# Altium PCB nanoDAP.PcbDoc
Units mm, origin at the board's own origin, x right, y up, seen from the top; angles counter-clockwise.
Board outline 76.68 x 40 mm, 2 copper layers (Top Layer, Bottom Layer); 20 components, 42 nets, 124 pads, 17 vias.
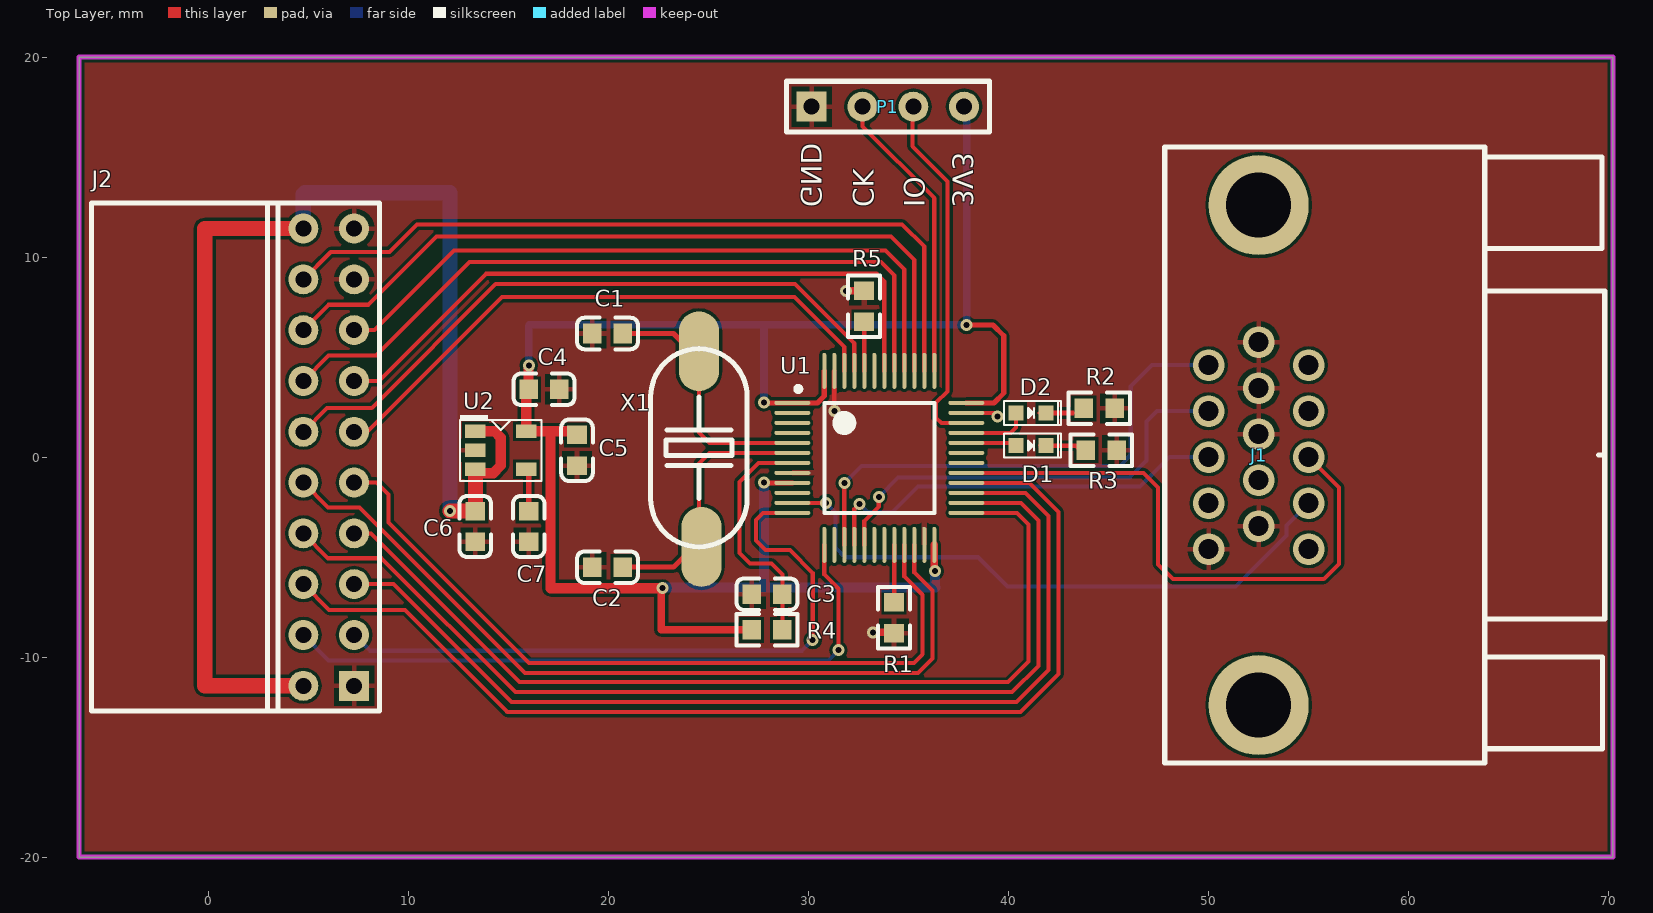
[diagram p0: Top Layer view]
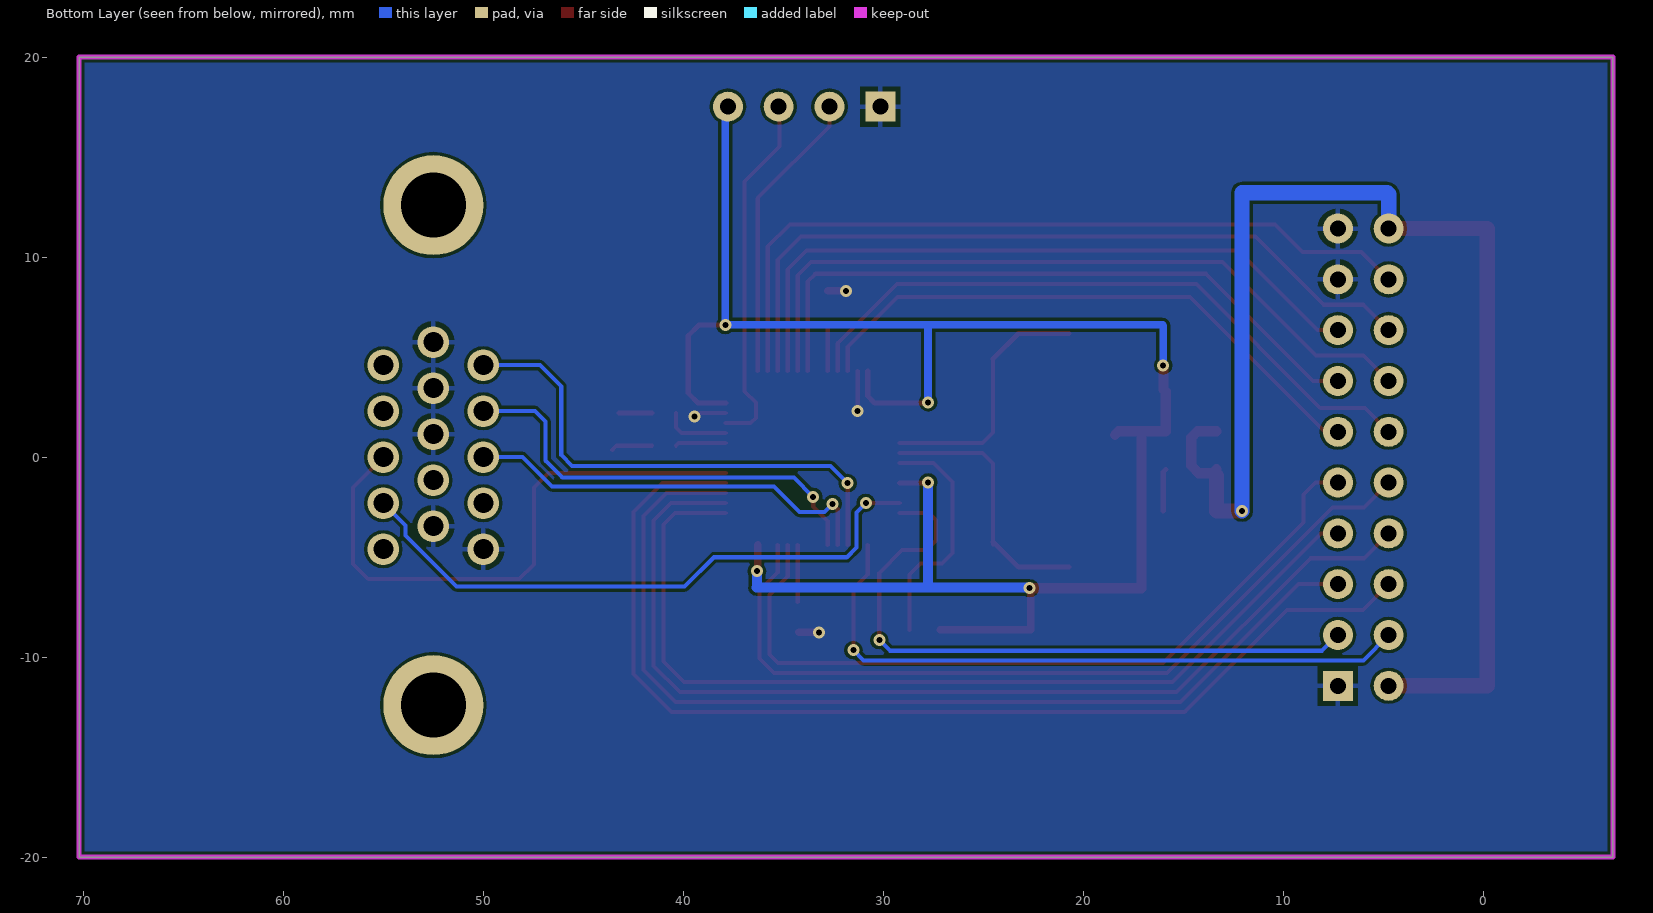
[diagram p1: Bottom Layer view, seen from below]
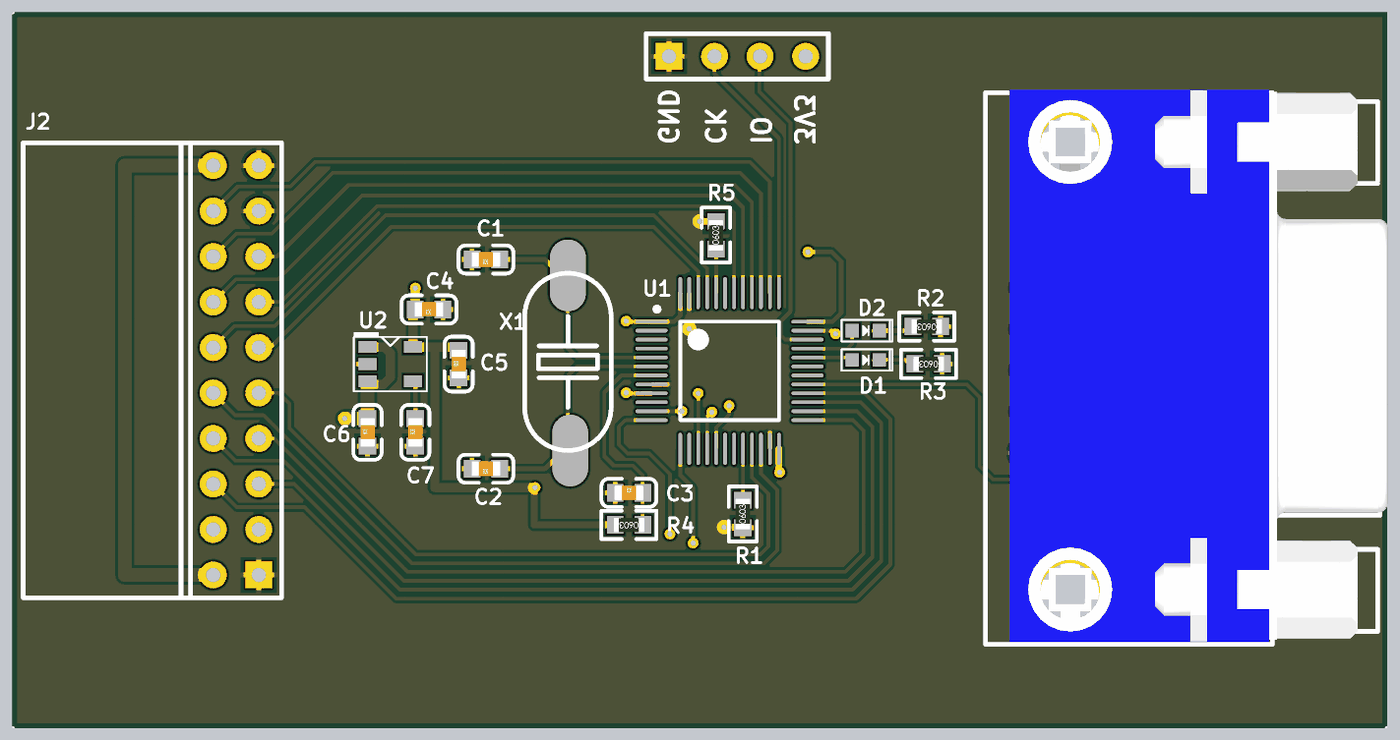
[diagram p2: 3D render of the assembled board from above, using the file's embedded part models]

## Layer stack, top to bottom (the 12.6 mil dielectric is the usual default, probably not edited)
Top Solder: solder mask 0.0102, Solder Resist, Dk 3.5
Top Layer: signal copper 0.0356
Dielectric 1: dielectric 0.32, FR-4, Dk 4.8
Bottom Layer: signal copper 0.0356
Bottom Solder: solder mask 0.0102, Solder Resist, Dk 3.5

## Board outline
-6.477,-20 -6.477,20 70.206,20 70.206,-20

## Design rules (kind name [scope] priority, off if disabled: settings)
Clearance [All] p1: gap=0.152 ignorepadtopadclearanceinfootprint=FALSE
DiffPairsRouting [All] p1: maxlimit=0.254 minlimit=0.254 mostfreqgap=0.254 toplayer_minwidth=0.203 toplayer_maxwidth=0.381 toplayer_prefwidth=0.381 bottomlayer_minwidth=0.203 bottomlayer_maxwidth=0.381 bottomlayer_prefwidth=0.381 maxuncoupledlength=12.7
HoleSize [All] p1 off: absolutevalues=TRUE maxlimit=2.54 minlimit=0.025 maxpercent=80.000 minpercent=20.000
PolygonConnect [All] p1: thpad.connectstyle=Relief thpad.reliefconductorwidth=0.254 thpad.reliefentries=4 thpad.polygonreliefangle="90 Angle" thpad.airgapwidth=0.254 smdpad.connectstyle=Relief smdpad.reliefconductorwidth=0.254 smdpad.reliefentries=4 smdpad.polygonreliefangle="90 Angle" smdpad.airgapwidth=0.254 via.connectstyle=Direct via.reliefconductorwidth=0.254 via.reliefentries=4 via.polygonreliefangle="90 Angle" via.airgapwidth=0.254
RoutingVias [All] p1: holewidth=0.3 width=0.6 viastyle="Through Hole" minholewidth=0.3 minwidth=0.6 maxholewidth=0.3 maxwidth=0.6
SolderMaskExpansion [All] p1: expansion=0.102
Width [All] p1: maxlimit=2.54 minlimit=0.152 preferedwidth=0.254
28 further rules are at their usual default settings.

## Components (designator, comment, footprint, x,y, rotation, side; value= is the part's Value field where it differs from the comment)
C1 "C0603" 0603_C 19.939,6.185 r180 top value=20pF
C2 "C0603" 0603_C 19.939,-5.499 r180 top value=20pF
C3 "C0603" 0603_C 27.915,-6.845 r0 top value=0.1uF
C4 "1uf" 0603_C 16.764,3.391 r180 top value=1uF
C5 "104" 0603_C 18.415,0.343 r90 top value=0.1uF
C6 "1uf" 0603_C 13.335,-3.467 r90 top value=1uF
C7 "223" 0603_C 16.002,-3.467 r90 top
D1 "RED" 0603_LED 41.123,0.572 r0 top
D2 "BLUE" 0603_LED 41.123,2.21 r0 top
J1 "VGA_FEMALE" VGA15B 50,0 r270 top
J2 "IDC20" IDC20 6,0 r90 top
P1 "Header 4" HEADER_4x1 30.15,17.526 r0 top
R1 "R0603" 0603_R 34.265,-8.026 r90 top value=10K
R2 "R0603" 0603_R 44.526,2.438 r180 top value=10K
R3 "R0603" 0603_R 44.628,0.356 r180 top value=10K
R4 "R0603" 0603_R 27.915,-8.636 r180 top value=10K
R5 "R0603" 0603_R 32.766,7.544 r90 top value=10K
U1 "STM32F103C8T6" LQFP48_N 33.528,-0.038 r0 top locked
U2 "RT9193-33" SOT23-5 14.605,0.343 r90 top
X1 "XTAL" 49SMD 24.511,0.47 r270 top value=8MHz

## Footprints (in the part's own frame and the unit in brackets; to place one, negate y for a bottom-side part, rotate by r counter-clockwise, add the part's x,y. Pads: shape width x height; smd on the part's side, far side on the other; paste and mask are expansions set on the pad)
49SMD [mm]
  oval 4x2 smd: 1(-4.826,0) 2(4.953,0.127)
  silkscreen extent -4.95,-2.41 4.95,2.41
0603_C [mm]
  rect 0.93x0.98 smd: 1(-0.77,0) 2(0.77,0)
  silkscreen extent -1.53,-0.79 1.54,0.79, body extent -0.8,-0.4 0.8,0.4, height 0.3
0603_LED [mm]
  rect 0.75x0.75 smd: 1(-0.75,0) 2(0.75,0)
  silkscreen extent -1.35,-0.6 1.5,0.6
0603_R [mm]
  rect 0.93x0.98 smd: 1(-0.77,0) 2(0.77,0)
  silkscreen extent -1.53,-0.79 1.54,0.79, body extent -0.85,-0.4 0.85,0.4, height 0.56
HEADER_4x1 [mm]
  rect 1.5x1.5 hole 0.8: 1(0,0)
  round 1.5 hole 0.8: 2(2.54,0) 3(5.08,0) 4(7.62,0)
  silkscreen extent -1.27,-1.27 8.89,1.27
IDC20 [mm]
  rect 1.5x1.5 hole 0.8: 1(-11.43,-1.27)
  round 1.5 hole 0.8: 2(-11.43,1.27) 3(-8.89,-1.27) 4(-8.89,1.27) 5(-6.35,-1.27) 6(-6.35,1.27) 7(-3.81,-1.27) 8(-3.81,1.27) 9(-1.27,-1.27) 10(-1.27,1.27) 11(1.27,-1.27) 12(1.27,1.27) 13(3.81,-1.27) 14(3.81,1.27) 15(6.35,-1.27) 16(6.35,1.27) 17(8.89,-1.27) 18(8.89,1.27) 19(11.43,-1.27) 20(11.43,1.27)
  silkscreen extent -12.7,-2.54 12.7,11.87
LQFP48_N [mm]
  oval 1.8x0.2 smd: 1(-4.35,2.75) 2(-4.35,2.25) 3(-4.35,1.75) 4(-4.35,1.25) 5(-4.35,0.75) 6(-4.35,0.25) 7(-4.35,-0.25) 8(-4.35,-0.75) 9(-4.35,-1.25) 10(-4.35,-1.75) 11(-4.35,-2.25) 12(-4.35,-2.75) 25(4.35,-2.75) 26(4.35,-2.25) 27(4.35,-1.75) 28(4.35,-1.25) 29(4.35,-0.75) 30(4.35,-0.25) 31(4.35,0.25) 32(4.35,0.75) 33(4.35,1.25) 34(4.35,1.75) 35(4.35,2.25) 36(4.35,2.75)
  oval 0.2x1.8 smd: 13(-2.75,-4.35) 14(-2.25,-4.35) 15(-1.75,-4.35) 16(-1.25,-4.35) 17(-0.75,-4.35) 18(-0.25,-4.35) 19(0.25,-4.35) 20(0.75,-4.35) 21(1.25,-4.35) 22(1.75,-4.35) 23(2.25,-4.35) 24(2.75,-4.35) 37(2.75,4.35) 38(2.25,4.35) 39(1.75,4.35) 40(1.25,4.35) 41(0.75,4.35) 42(0.25,4.35) 43(-0.25,4.35) 44(-0.75,4.35) 45(-1.25,4.35) 46(-1.75,4.35) 47(-2.25,4.35) 48(-2.75,4.35)
  silkscreen extent -4.17,-2.75 2.75,3.57
SOT23-5 [mil]
  rect 26x40 smd: 1(37.4,50) 2(0,50) 3(-37.4,50) 4(-37.4,-50) 5(37.4,-50)
  silkscreen extent -60,-80 70,80
VGA15B [mm] "15针通讯接口"
  round 1.58 hole 1: 1(-4.6,0) 2(-2.3,0) 3(0,0) 4(2.3,0) 5(4.6,0) 6(-5.75,2.5) 7(-3.45,2.5) 8(-1.15,2.5) 9(1.15,2.5) 10(3.45,2.5) 11(-4.6,5) 12(-2.3,5) 13(0,5) 14(2.3,5) 15(4.6,5)
  round 5 hole 3.25: 16(-12.6,2.5) 17(12.4,2.5)
  silkscreen extent -15.5,-2.2 15.3,19.8, body extent -15.66,-0.87 15.15,20.23, height 12.77

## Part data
C1 C2 C3: "Capacitor"
C4 C5 C6 C7: library part CAP, "Capacitor"
D1 D2: library part D0603, "Typical RED, GREEN, YELLOW, AMBER GaAs LED"
P1: "Header, 4-Pin"
R1 R2 R3 R4 R5: "Resistor"
U1: "LowPower MCU"

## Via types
v1: diameter 0.6, hole 0.3, Top Layer to Bottom Layer, 17 vias

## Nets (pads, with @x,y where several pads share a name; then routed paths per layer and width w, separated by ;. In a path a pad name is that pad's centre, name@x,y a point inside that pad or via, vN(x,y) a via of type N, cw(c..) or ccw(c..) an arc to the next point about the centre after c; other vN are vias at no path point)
3V3: C4.2 C5.2 P1.4 R4.2 U1.1 U1.9 U1.24 U1.36 U1.48 U2.5 | length 98.5
  Top Layer w0.254: v1(27.762,-1.257) 27.793,-1.288 U1.9 ; v1@27.793,2.712 U1.1 30.436,2.712 30.778,3.054 U1.48 ; v1@36.278,-5.658 v1(36.322,-5.702) ; U1.36 39.262,2.712 39.751,3.2 39.751,6.071 39.218,6.604 v1(37.897,6.604)
  Top Layer w0.381: v1(22.682,-6.553) 22.631,-6.604 22.631,-8.636 R4.2 ; v1@36.278,-5.658 U1.24
  Top Layer w0.508: v1(16.002,4.585) 15.994,4.577 C4.2 15.875,3.272 U2.5 17.094,1.293 ; C5.2 18.235,1.293 17.094,1.293 ; v1(22.682,-6.553) 17.094,-6.553 17.094,1.293
  Bottom Layer w0.381: v1(16.002,4.585) 16.002,6.579 16.04,6.617 37.884,6.617 v1(37.897,6.604) ; v1(27.762,2.743) 27.762,6.566 ; v1@37.91,6.617 P1.4@37.91,17.526
  Bottom Layer w0.508: v1@22.708,-6.523 27.762,-6.523 ; v1(27.762,-1.257) 27.762,-6.523 ; v1(36.322,-5.702) 36.322,-6.504 36.341,-6.523 27.762,-6.523
5V: C6.2 J2.2 J2.20 U2.1 U2.3 | length 65.1
  Top Layer w0.508: U2.3 13.528,-0.8 14.224,-0.8 14.605,-0.419 14.605,0.978 14.29,1.293 U2.1
  Top Layer w0.762: J2.2 -0.203,-11.43 -0.203,11.43 J2.20 ; v1(12.058,-2.697) C6.2 U2.3@13.335,-0.927
  Bottom Layer w0.762: J2.20 4.73,13.15 4.807,13.227 12.058,13.227 v1(12.058,-2.697)
BOOT0: R5.1 U1.44 | length 2.4
  Top Layer w0.203: U1.44 R5.1@32.778,6.694
BOOT1: R1.2 U1.20 | length 2.9
  Top Layer w0.203: R1.2@34.278,-7.243 U1.20
D_SWCLK: P1.2 U1.37 | length 14.7
  Top Layer w0.203: P1.2 32.69,16.535 36.278,12.947 U1.37
D_SWDIO: P1.3 U1.34 | length 18.1
  Top Layer w0.203: P1.3 35.179,17.475 35.179,15.545 36.932,13.792 36.932,3.288 36.373,2.73 36.373,1.968 36.629,1.712 U1.34
GND: C1.2 C2.2 C3.1 C4.1 C5.1 C6.1 C7.1 J1.5 J1.6 J1.7 J1.8 J1.10 J2.1 J2.17 J2.19 P1.1 R1.1 R2.1 R3.1 R5.2 U1.8 U1.23 U1.35 U1.47 U2.2 | length 5.6
  Top Layer w0.203: v1(31.278,2.311) U1.47 ; R1.1@34.231,-8.763 R1.1 ; U1.35 39.266,2.212 v1(39.446,2.032)
  Top Layer w0.381: v1@31.852,8.306 v1(31.86,8.314) R5.2 ; v1(33.223,-8.763) R1.1@34.231,-8.763
LED_CON: D2.1 U1.33 | length 3.3
  Top Layer w0.203: U1.33 40.099,1.212 40.373,1.485 D2.1
LED_RUN: D1.1 U1.32 | length 2.6
  Top Layer w0.203: U1.32 40.232,0.712 D1.1
NetC1_1: C1.1 U1.5 X1.1 | length 12.9
  Top Layer w0.203: X1.1@24.511,4.915 24.511,1.232 25.031,0.712 U1.5
  Top Layer w0.254: C1.1 23.241,6.185 X1.1@24.511,4.915
NetC2_1: C2.1 U1.6 X1.2 | length 13.3
  Top Layer w0.203: X1.2@24.511,-4.372 24.511,-0.308 25.031,0.212 U1.6
  Top Layer w0.254: C2.1 23.241,-5.499 X1.2@24.511,-4.229
NetC3_2: C3.2 R4.1 U1.7 | length 11.9
  Top Layer w0.203: R4.1 28.685,-5.863 28.143,-5.321 27.064,-5.321 26.543,-4.801 26.543,-1.232 27.487,-0.288 U1.7
NetC7_2: C7.2 U2.4 | length 2.1
  Top Layer w0.254: U2.4 16.002,-0.734 C7.2
NetD1_2: D1.2 R3.2 | length 2.1
  Top Layer w0.203: D1.2@41.568,0.572 43.337,0.572 R3.2@43.553,0.356
NetD2_2: D2.2 R2.2 | length 1.7
  Top Layer w0.254: D2.2@41.568,2.21 43.223,2.21
PA0: U1.10
PA1: J1.14 U1.11 | length 30.6
  Top Layer w0.203: U1.11 v1(30.869,-2.288)
  Bottom Layer w0.203: v1(30.869,-2.288) 31.344,-2.762 31.344,-4.521 31.826,-5.004 38.456,-5.004 39.929,-6.477 51.333,-6.477 53.894,-3.917 53.894,-3.406 J1.14
PA4: U1.14
PA5: J1.1 U1.15 | length 25.8
  Top Layer w0.203: U1.15 v1(31.778,-1.295)
  Bottom Layer w0.203: v1(31.778,-1.295) 32.642,-0.432 45.568,-0.432 46.101,0.102 46.101,3.531 47.17,4.6 J1.1
PA6: J1.3 U1.16 | length 20.9
  Top Layer w0.203: U1.16 32.278,-2.596 v1(32.537,-2.337)
  Bottom Layer w0.203: v1(32.537,-2.337) 32.944,-2.743 34.188,-2.743 35.458,-1.473 46.558,-1.473 48.031,0 J1.3
PA7: J1.2 U1.17 | length 22.1
  Top Layer w0.203: U1.17 32.778,-3.188 33.503,-2.464 v1(33.503,-1.981)
  Bottom Layer w0.203: v1(33.503,-1.981) 34.468,-1.016 46.05,-1.016 46.888,-0.178 46.888,1.778 47.41,2.3 J1.2
PA8: J1.13 U1.29 | length 29.4
  Top Layer w0.203: U1.29 46.737,-0.788 47.473,-1.524 47.473,-5.359 48.209,-6.096 55.753,-6.096 56.515,-5.334 56.515,-1.515 J1.13
PA9: U1.30
PA10: U1.31
PA15: J2.18 U1.38 | length 38.9
  Top Layer w0.203: J2.18 6.102,10.262 9.042,10.262 10.414,11.633 34.671,11.633 35.778,10.526 U1.38
PB0: U1.18
PB1: U1.19
PB3: J2.16 U1.39 | length 38.5
  Top Layer w0.203: J2.16 6,7.62 7.976,7.62 11.379,11.024 34.112,11.024 35.278,9.858 U1.39
PB4: J2.15 U1.40 | length 34.6
  Top Layer w0.203: J2.15 8.28,6.35 12.268,10.338 33.833,10.338 34.778,9.393 U1.40
PB5: J2.14 U1.41 | length 37.1
  Top Layer w0.203: J2.14 6,5.08 8.357,5.08 13.03,9.754 33.604,9.754 34.278,9.08 U1.41
PB6: J2.13 U1.42 | length 33.4
  Top Layer w0.203: J2.13 8.509,3.81 13.868,9.169 33.401,9.169 33.778,8.792 U1.42
PB7: U1.43
PB8: J2.12 U1.45 | length 33.2
  Top Layer w0.203: J2.12 5.924,2.464 8.153,2.464 14.351,8.661 29.312,8.661 32.278,5.695 U1.45
PB9: J2.11 U1.46 | length 29.5
  Top Layer w0.203: J2.11 7.925,1.27 14.656,8.001 29.286,8.001 31.778,5.509 U1.46
PB10: J2.9 U1.21 | length 39
  Top Layer w0.203: J2.9 8.382,-1.27 8.986,-1.874 8.986,-3.257 16.016,-10.287 35.255,-10.287 35.687,-9.855 35.687,-6.879 34.778,-5.97 U1.21
PB11: J2.10 U1.22 | length 41.7
  Top Layer w0.203: J2.10 5.975,-2.515 7.537,-2.515 15.809,-10.787 35.462,-10.787 36.187,-10.062 36.187,-6.672 35.278,-5.763 U1.22
PB12: J2.7 U1.25 | length 47.4
  Top Layer w0.203: J2.7 8.108,-3.81 15.549,-11.251 39.968,-11.251 40.994,-10.224 40.994,-3.365 40.418,-2.788 U1.25
PB13: J2.8 U1.26 | length 51.9
  Top Layer w0.203: J2.8 5.975,-5.055 8.646,-5.055 15.342,-11.751 40.175,-11.751 41.494,-10.432 41.494,-3.157 40.625,-2.288 U1.26
PB14: J2.5 U1.27 | length 50.1
  Top Layer w0.203: J2.5 9.234,-6.35 15.135,-12.251 40.382,-12.251 41.994,-10.639 41.994,-2.95 40.832,-1.788 U1.27
PB15: J2.6 U1.28 | length 54.5
  Top Layer w0.203: J2.6 6.025,-7.645 9.822,-7.645 14.928,-12.751 40.589,-12.751 42.494,-10.846 42.494,-2.743 41.039,-1.288 U1.28
UART2_RX: J2.4 U1.13 | length 33.1
  Top Layer w0.203: U1.13 30.778,-5.861 31.496,-6.579 v1(31.496,-9.652)
  Bottom Layer w0.203: J2.4 6,-10.16 30.988,-10.16 v1(31.496,-9.652)
UART2_TX: J2.3 U1.12 | length 33.3
  Top Layer w0.203: U1.12 27.717,-2.788 27.356,-3.15 27.356,-4.166 27.838,-4.648 29.058,-4.648 30.201,-5.791 v1(30.201,-9.144)
  Bottom Layer w0.203: J2.3 8.057,-9.677 29.667,-9.677 v1(30.201,-9.144)
pads on no net: J1.4 J1.9 J1.11 J1.12 J1.15 J1.16 J1.17 U1.2 U1.3 U1.4

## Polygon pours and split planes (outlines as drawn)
GND on Top Layer "GND_L01_P000" (solid, remove dead copper, pour order 0): -6.477,-20 -6.477,20 70.206,20 70.206,-20
GND on Bottom Layer "GND_L02_P002" (solid, remove dead copper, pour order 2): -6.477,-20 -6.477,20 70.206,20 70.206,-20

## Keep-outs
Keep-Out Layer:
  the board outline again, w0.254

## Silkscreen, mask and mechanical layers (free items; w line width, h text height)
Top Overlay:
  text "GND" at 29.616,12.484 h1.02 r270
  text "CK" at 32.233,12.484 h1.02 r270
  text "IO" at 34.773,12.484 h1.02 r270
  text "3V3" at 37.211,12.484 h1.02 r270

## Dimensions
-6.477,-20 to 70.206,-20 on Top Overlay
-6.477,20 to -6.477,-20 on Top Overlay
